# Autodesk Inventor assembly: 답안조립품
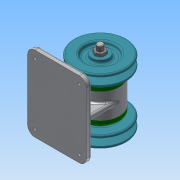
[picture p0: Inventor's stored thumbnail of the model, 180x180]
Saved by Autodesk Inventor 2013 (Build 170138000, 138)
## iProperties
Created: 2019-09
Part Number: 답안조립품
Document SubType Name: Assembly
Designer: Administrator
Author: Administrator
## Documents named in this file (10)
- C:\Users\Administrator\Desktop\490904V1043\답안조립품.iam
- C:\Users\Administrator\Desktop\490904V1043\본체.ipt
- C:\Users\Administrator\Desktop\490904V1043\V-벨트풀리.ipt
- C:\Users\Administrator\Desktop\490904V1043\너트 M10x1.ipt
- C:\Users\Administrator\Desktop\490904V1043\베어링 6004.ipt
- C:\Users\Administrator\Desktop\490904V1043\볼트 M4.ipt
- C:\Users\Administrator\Desktop\490904V1043\오일 실 17 30 5.ipt
- C:\Users\Administrator\Desktop\490904V1043\축.ipt
- C:\Users\Administrator\Desktop\490904V1043\커버.ipt
- C:\Users\Administrator\Desktop\490904V1043\키 5 x 5 x 12.ipt
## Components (2 placed, 1 different names)
1. V-벨트풀리:1
2. V-벨트풀리:2
